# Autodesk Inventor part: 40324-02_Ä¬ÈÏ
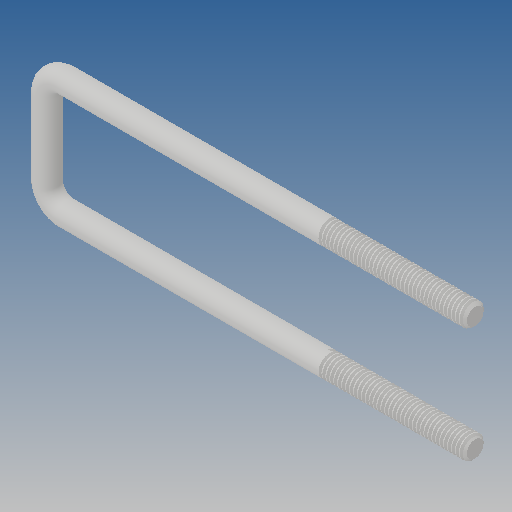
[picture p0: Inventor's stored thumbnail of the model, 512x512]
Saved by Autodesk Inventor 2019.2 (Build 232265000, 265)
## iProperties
Created: 2010-06
Part Number: 40324-02_Ä¬ÈÏ
Material: Ogólny
Document SubType Name: Modeling
Designer: CADENGINEERING4
Density: 1 g/cm^3
Appearance: Domyślna
Author: CADENGINEERING4
Revision Number: ÈÎºÎ
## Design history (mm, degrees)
feature "NONE"
node "Bryła1"
